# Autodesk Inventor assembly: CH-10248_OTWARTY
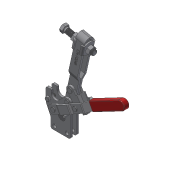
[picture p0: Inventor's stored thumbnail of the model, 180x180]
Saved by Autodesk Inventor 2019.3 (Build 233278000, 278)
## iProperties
Company: Î¢ÈíÖÐ¹ú
Created: 2012-09
Part Number: CH-10248_OTWARTY
Material: Ogólny
Description: STEP AP203
Document SubType Name: Assembly
Designer: CADENGINEERING4
Sending System: SolidWorks 2010
Preprocessor: SwSTEP 2.0
Title: CH-10248.STEP
Author: Î¢ÈíÓÃ»§
Revision Number: ÈÎºÎ
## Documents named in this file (18)
- D:\Vault_2016\Projekty\NASZ KATALOG\CLAMPTEK\STRONA\Vertical toggle clamp\CH-10248\CH-10248_OTWARTY.iam
- D:\Vault_2016\Projekty\NASZ KATALOG\CLAMPTEK\STEP FILES\Vertical toggle clamp\CH-10248\CH-10247-09.ipt
- D:\Vault_2016\Projekty\NASZ KATALOG\CLAMPTEK\STEP FILES\Vertical toggle clamp\CH-10248\CH-FW-120.ipt
- D:\Vault_2016\Projekty\NASZ KATALOG\CLAMPTEK\STEP FILES\Vertical toggle clamp\CH-10248\CH-10248-01 STRAIGHT BASE.ipt
- D:\Vault_2016\Projekty\NASZ KATALOG\CLAMPTEK\STEP FILES\Vertical toggle clamp\CH-10248\CH-10247-10.ipt
- D:\Vault_2016\Projekty\NASZ KATALOG\CLAMPTEK\STEP FILES\Vertical toggle clamp\CH-10248\CH-10247-08.ipt
- D:\Vault_2016\Projekty\NASZ KATALOG\CLAMPTEK\STEP FILES\Vertical toggle clamp\CH-10248\CH-10247-06.ipt
- D:\Vault_2016\Projekty\NASZ KATALOG\CLAMPTEK\STEP FILES\Vertical toggle clamp\CH-10248\CH-10247-03 HANDLE.ipt
- D:\Vault_2016\Projekty\NASZ KATALOG\CLAMPTEK\STEP FILES\Vertical toggle clamp\CH-10248\CH-10247-04 CONNECTING-PLATE.ipt
- D:\Vault_2016\Projekty\NASZ KATALOG\CLAMPTEK\STEP FILES\Vertical toggle clamp\CH-10248\3-8-16 LOCK NUT.ipt
- D:\Vault_2016\Projekty\NASZ KATALOG\CLAMPTEK\STEP FILES\Vertical toggle clamp\CH-10248\CH-10247-11.ipt
- D:\Vault_2016\Projekty\NASZ KATALOG\CLAMPTEK\STEP FILES\Vertical toggle clamp\CH-10248\CH-10247-07.ipt
- D:\Vault_2016\Projekty\NASZ KATALOG\CLAMPTEK\STEP FILES\Vertical toggle clamp\CH-10248\CH-10248-02 U-BAR.ipt
- D:\Vault_2016\Projekty\NASZ KATALOG\CLAMPTEK\STEP FILES\Vertical toggle clamp\CH-10248\CH-SA-12300 SPINDLE SUPPLIED.ipt
- D:\Vault_2016\Projekty\NASZ KATALOG\CLAMPTEK\STEP FILES\Vertical toggle clamp\CH-10248\CH-SA-12300 NUT.ipt
- D:\Vault_2016\Projekty\NASZ KATALOG\CLAMPTEK\STEP FILES\Vertical toggle clamp\CH-10248\M6X25.ipt
- D:\Vault_2016\Projekty\NASZ KATALOG\CLAMPTEK\STEP FILES\Vertical toggle clamp\CH-10248\M6 Nut.ipt
- D:\Vault_2016\Projekty\NASZ KATALOG\CLAMPTEK\STEP FILES\Vertical toggle clamp\CH-10248\CH-10247-05.ipt
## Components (23 placed, 17 different names)
1. CH-10247-09_1
2. CH-10248-01 STRAIGHT BASE_3
3. M6X25_19
4. M6 Nut_22
5. CH-FW-120:3 — Zestawiające:26, Zestawiające:27, Zestawiające:30, Kątowe:1, Równoległe:3
6. CH-10247-10:2 — Zestawiające:43, Zestawiające:44, Zestawiające:45
7. CH-10247-08:3 — Zestawiające:15, Zestawiające:16, Zestawiające:17, Zestawiające:31, Zestawiające:32, Zestawiające:40
8. CH-10247-06:3 — Zestawiające:7, Zestawiające:8, Równoległe:1
9. CH-10247-03 HANDLE:2 — Zestawiające:4, Zestawiające:5, Zestawiające:6, Zestawiające:17, Zestawiające:18, Zestawiające:20, Zestawiające:21, Zestawiające:31, Zestawiające:32, Zestawiające:39, Zestawiające:43, Zestawiające:44, Zestawiające:45
10. CH-10247-04 CONNECTING-PLATE:2 — Zestawiające:9, Zestawiające:10, Zestawiające:11, Zestawiające:14, Zestawiające:18, Zestawiające:19, Zestawiające:22, Zestawiające:37, Zestawiające:47
11. 3-8-16 LOCK NUT:3 — Zestawiające:21, Zestawiające:40
12. CH-10247-11:3 — Zestawiające:10, Zestawiające:11, Zestawiające:12, Zestawiające:13, Zestawiające:14, Zestawiające:33, Zestawiające:34, Zestawiające:38, Zestawiające:46
13. CH-10247-07:2 — Zestawiające:1, Zestawiające:2, Zestawiające:5
14. CH-10248-02 U-BAR:2 — Zestawiające:8, Równoległe:1, Zestawiające:19, Zestawiające:22, Zestawiające:27, Zestawiające:28, Równoległe:2, Zestawiające:35, Zestawiające:36, Kątowe:1, Zestawiające:38
15. CH-10247-08:4 — Zestawiające:1, Zestawiające:2, Zestawiające:3, Zestawiające:4, Zestawiające:39
16. CH-SA-12300 SPINDLE SUPPLIED:2 — Zestawiające:23, Równoległe:2
17. CH-SA-12300 NUT:3 — Zestawiające:23, Zestawiające:24, Zestawiające:30, Zestawiające:35, Zestawiające:36
18. CH-10247-06:4 — Zestawiające:12, Zestawiające:13, Zestawiające:33, Zestawiające:34, Zestawiające:46, Zestawiające:47
19. CH-SA-12300 NUT:4 — Zestawiające:24, Zestawiające:25, Zestawiające:26, Zestawiające:29
20. CH-FW-120:4 — Zestawiające:25, Zestawiające:28, Zestawiające:29, Równoległe:3
21. CH-10247-11:4 — Zestawiające:7, Zestawiające:9
22. 3-8-16 LOCK NUT:4 — Zestawiające:3, Zestawiające:6
23. CH-10247-05:2 — Zestawiające:15, Zestawiające:16, Zestawiające:20, Zestawiające:37
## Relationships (49: Mate 45, Flush 3, Angle 1)
- Zestawiające:1 [Mate]: CH-10247-07:2 ↔ CH-10247-08:4
- Zestawiające:2 [Mate]: CH-10247-07:2 ↔ CH-10247-08:4
- Zestawiające:3 [Mate]: CH-10247-08:4 ↔ 3-8-16 LOCK NUT:4
- Zestawiające:4 [Mate]: CH-10247-03 HANDLE:2 ↔ CH-10247-08:4
- Zestawiające:5 [Mate]: CH-10247-03 HANDLE:2 ↔ CH-10247-07:2
- Zestawiające:6 [Mate]: CH-10247-03 HANDLE:2 ↔ 3-8-16 LOCK NUT:4
- Zestawiające:7 [Mate]: CH-10247-06:3 ↔ CH-10247-11:4
- Zestawiające:8 [Mate]: CH-10247-06:3 ↔ CH-10248-02 U-BAR:2
- Równoległe:1 [Flush]: CH-10247-06:3 ↔ CH-10248-02 U-BAR:2
- Zestawiające:9 [Mate]: CH-10247-04 CONNECTING-PLATE:2 ↔ CH-10247-11:4
- Zestawiające:10 [Mate]: CH-10247-04 CONNECTING-PLATE:2 ↔ CH-10247-11:3
- Zestawiające:11 [Mate]: CH-10247-04 CONNECTING-PLATE:2 ↔ CH-10247-11:3
- Zestawiające:12 [Mate]: CH-10247-11:3 ↔ CH-10247-06:4
- Zestawiające:13 [Mate]: CH-10247-11:3 ↔ CH-10247-06:4
- Zestawiające:14 [Mate]: CH-10247-04 CONNECTING-PLATE:2 ↔ CH-10247-11:3
- Zestawiające:15 [Mate]: CH-10247-08:3 ↔ CH-10247-05:2
- Zestawiające:16 [Mate]: CH-10247-08:3 ↔ CH-10247-05:2
- Zestawiające:17 [Mate]: CH-10247-08:3 ↔ CH-10247-03 HANDLE:2
- Zestawiające:18 [Mate]: CH-10247-03 HANDLE:2 ↔ CH-10247-04 CONNECTING-PLATE:2
- Zestawiające:19 [Mate]: CH-10247-04 CONNECTING-PLATE:2 ↔ CH-10248-02 U-BAR:2
- Zestawiające:20 [Mate]: CH-10247-03 HANDLE:2 ↔ CH-10247-05:2
- Zestawiające:21 [Mate]: CH-10247-03 HANDLE:2 ↔ 3-8-16 LOCK NUT:3
- Zestawiające:22 [Mate]: CH-10247-04 CONNECTING-PLATE:2 ↔ CH-10248-02 U-BAR:2
- Zestawiające:23 [Mate]: CH-SA-12300 SPINDLE SUPPLIED:2 ↔ CH-SA-12300 NUT:3
- Zestawiające:24 [Mate]: CH-SA-12300 NUT:3 ↔ CH-SA-12300 NUT:4
- Zestawiające:25 [Mate]: CH-SA-12300 NUT:4 ↔ CH-FW-120:4
- Zestawiające:26 [Mate]: CH-FW-120:3 ↔ CH-SA-12300 NUT:4
- Zestawiające:27 [Mate]: CH-FW-120:3 ↔ CH-10248-02 U-BAR:2
- Zestawiające:28 [Mate]: CH-10248-02 U-BAR:2 ↔ CH-FW-120:4
- Zestawiające:29 [Mate]: CH-SA-12300 NUT:4 ↔ CH-FW-120:4
- Zestawiające:30 [Mate]: CH-FW-120:3 ↔ CH-SA-12300 NUT:3
- Równoległe:2 [Flush]: CH-10248-02 U-BAR:2 ↔ CH-SA-12300 SPINDLE SUPPLIED:2
- Zestawiające:31 [Mate]: CH-10247-08:3 ↔ CH-10247-03 HANDLE:2
- Zestawiające:32 [Mate]: CH-10247-08:3 ↔ CH-10247-03 HANDLE:2
- Zestawiające:33 [Mate]: CH-10247-11:3 ↔ CH-10247-06:4
- Zestawiające:34 [Mate]: CH-10247-11:3 ↔ CH-10247-06:4
- Zestawiające:35 [Mate]: CH-10248-02 U-BAR:2 ↔ CH-SA-12300 NUT:3
- Zestawiające:36 [Mate]: CH-10248-02 U-BAR:2 ↔ CH-SA-12300 NUT:3
- Kątowe:1 [Angle]: CH-FW-120:3 ↔ CH-10248-02 U-BAR:2
- Zestawiające:37 [Mate]: CH-10247-04 CONNECTING-PLATE:2 ↔ CH-10247-05:2
- Zestawiające:38 [Mate]: CH-10247-11:3 ↔ CH-10248-02 U-BAR:2
- Zestawiające:39 [Mate]: CH-10247-03 HANDLE:2 ↔ CH-10247-08:4
- Zestawiające:40 [Mate]: CH-10247-08:3 ↔ 3-8-16 LOCK NUT:3
- Zestawiające:43 [Mate]: CH-10247-10:2 ↔ CH-10247-03 HANDLE:2
- Zestawiające:44 [Mate]: CH-10247-10:2 ↔ CH-10247-03 HANDLE:2
- Zestawiające:45 [Mate]: CH-10247-10:2 ↔ CH-10247-03 HANDLE:2
- Zestawiające:46 [Mate]: CH-10247-11:3 ↔ CH-10247-06:4
- Zestawiające:47 [Mate]: CH-10247-04 CONNECTING-PLATE:2 ↔ CH-10247-06:4
- Równoległe:3 [Flush]: CH-FW-120:3 ↔ CH-FW-120:4
